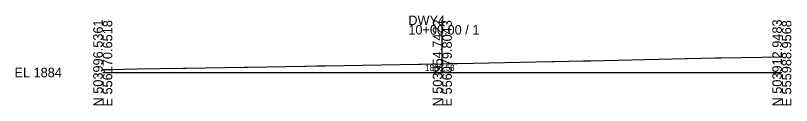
# Model space of a CAD drawing. Extents: x -26 to 556133, y -10 to 503926.
# Drawn here: x -25.7 to 202.8, y -9.7 to 16.8 of the extents above; entities that cross this region are included whole.
import ezdxf

# ---------------------------------------------------------------- set-up
doc = ezdxf.new("R2010")
doc.units = 0
for name, color, linetype in [('Default', 7, 'Continuous'), ('Exist Cross Section Cell', 7, 'Continuous'), ('Exist XS Center Line Elevation Label', 7, 'Continuous'), ('Exist XS Ground Line', 7, 'Continuous')]:
    doc.layers.add(name, color=color, linetype=linetype)

msp = doc.modelspace()

# ---------------------------------------------------------------- linework, layer by layer
at = {"layer": 'Exist Cross Section Cell'}
for p, q in [((100, 0), (100, 13.96)), ((0, 0), (100, 0)), ((100, 0), (200, 0))]:
    msp.add_line(p, q, dxfattribs=at)
at = {"layer": 'Exist XS Ground Line'}
for p, q in [((182.16, 4.35), (200, 4.65)), ((65.49, 1.99), (93.08, 2.45)), ((93.08, 2.45), (93.73, 2.46)), ((93.73, 2.46), (100, 2.58)), ((100, 2.58), (102.27, 2.63)), ((102.27, 2.63), (104.45, 2.67)), ((104.45, 2.67), (132.26, 3.19)), ((132.26, 3.19), (132.95, 3.21)), ((132.95, 3.21), (141.6, 3.42)), ((141.6, 3.42), (143.74, 3.47)), ((143.74, 3.47), (171.6, 4.16)), ((171.6, 4.16), (172.16, 4.17)), ((172.16, 4.17), (180.32, 4.31)), ((180.32, 4.31), (182.16, 4.35)), ((0, 0.83), (6, 0.96)), ((6, 0.96), (10.1, 1.04)), ((10.1, 1.04), (23.79, 1.27)), ((23.79, 1.27), (24.53, 1.29)), ((24.53, 1.29), (41.63, 1.58)), ((41.63, 1.58), (42.72, 1.6)), ((42.72, 1.6), (59.48, 1.89)), ((59.48, 1.89), (59.78, 1.89)), ((59.78, 1.89), (63.08, 1.95)), ((63.08, 1.95), (65.49, 1.99))]:
    msp.add_line(p, q, dxfattribs=at)

# ---------------------------------------------------------------- texts
at = {"layer": 'Default'}
msp.add_text('-', height=0.0001, dxfattribs=at).set_placement((0, 0))
at = {"layer": 'Exist Cross Section Cell'}
for s, p in [('DWY4', (90, 13.96)), ('10+00.00 / 1', (90, 11.16)), ('EL 1884', (-26, -1.4))]:
    msp.add_text(s, height=2.8, dxfattribs=at).set_placement(p)
for s, p in [('N 503996.5361', (0, -10)), ('E 556170.6518', (2.8, -10)), ('N 503954.7422', (100, -10)), ('E 556079.8043', (102.8, -10)), ('N 503912.9483', (200, -10)), ('E 555988.9568', (202.8, -10))]:
    msp.add_text(s, height=2.8, rotation=90, dxfattribs=at).set_placement(p)
at = {"layer": 'Exist XS Center Line Elevation Label'}
msp.add_text('1886.58', height=1.8, dxfattribs=at).set_placement((94.91, 0.48))

doc.saveas('drawing.dxf')
